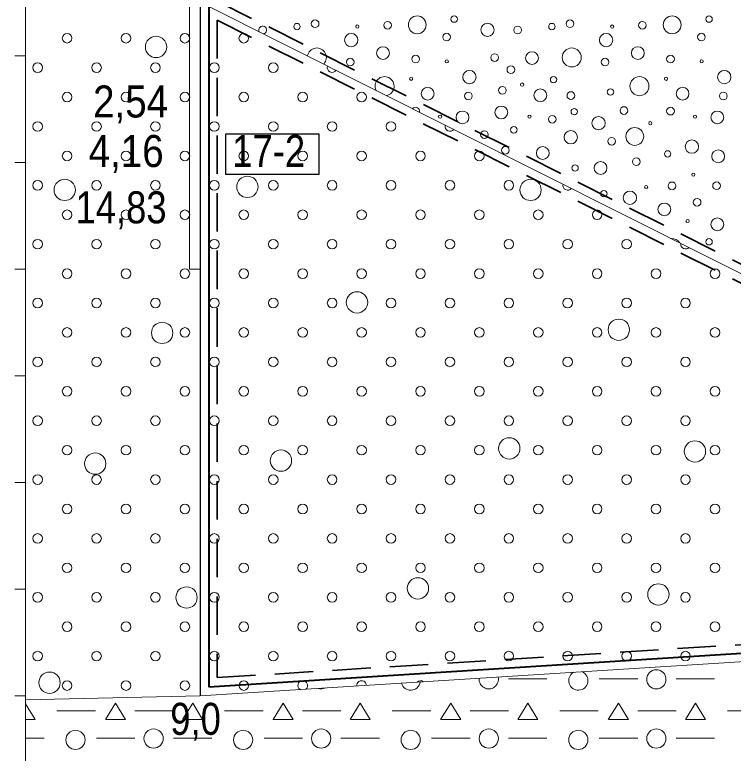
# Model space of a CAD drawing. Extents: x 640104 to 640970, y 6442278 to 6442689.
# Drawn here: x 640552.7 to 640620, y 6442553.6 to 6442622.8 of the extents above; entities that cross this region are included whole.
import ezdxf
from ezdxf.enums import TextEntityAlignment as Align

# ---------------------------------------------------------------- set-up
doc = ezdxf.new("R2010")
doc.units = 0
doc.header["$LTSCALE"] = 1.2
doc.linetypes.add('MEDIUM_DASHED', pattern=[4.5, 3, -1.5])
for name, color, linetype, lineweight in [('30', 7, 'Continuous', 13), ('31', 7, 'Continuous', 13), ('32', 7, 'Continuous', 25), ('33', 7, 'Continuous', 13), ('35', 7, 'Continuous', 35), ('41', 7, 'Continuous', 13), ('42', 7, 'Continuous', 13), ('46', 7, 'Continuous', 13), ('47', 7, 'Continuous', 13)]:
    doc.layers.add(name, color=color, linetype=linetype, lineweight=lineweight)

msp = doc.modelspace()

# ---------------------------------------------------------------- linework, layer by layer
at = {"layer": '30'}
for p, q in [((640553.71, 6442488.94), (640553.71, 6442658.94)), ((640552.71, 6442618.94), (640553.71, 6442618.94)), ((640552.71, 6442608.94), (640553.71, 6442608.94)), ((640552.71, 6442598.94), (640553.71, 6442598.94)), ((640552.71, 6442588.94), (640553.71, 6442588.94)), ((640552.71, 6442578.94), (640553.71, 6442578.94)), ((640552.71, 6442568.94), (640553.71, 6442568.94)), ((640552.71, 6442558.94), (640553.71, 6442558.94))]:
    msp.add_line(p, q, dxfattribs=at)
at = {"layer": '31'}
for points in [[(640553.71, 6442623.86), (640570.01, 6442624), (640649.72, 6442583.95), (640760.57, 6442587.97)], [(640553.71, 6442558.56), (640570.07, 6442558.94), (640649.85, 6442563.98), (640763.79, 6442536.22), (640808.67, 6442524.48), (640822.17, 6442520.94), (640837.77, 6442517.67), (640873.2, 6442509.45), (640884.27, 6442508.94), (640895.27, 6442508.94), (640947.47, 6442510.44), (640955.05, 6442510.44)]]:
    msp.add_lwpolyline(points, dxfattribs=at)
at = {"layer": '32'}
msp.add_line((640570.07, 6442648.94), (640570.07, 6442558.94), dxfattribs=at)
at = {"layer": '33'}
msp.add_lwpolyline([(640569.07, 6442623.94), (640569.07, 6442598.94), (640570.07, 6442598.94), (640570.07, 6442623.94), (640570.01, 6442623.94)], close=True, dxfattribs=at)
at = {"layer": '33', "lineweight": 25}
msp.add_lwpolyline([(640572.48, 6442611.61), (640581.19, 6442611.61), (640581.19, 6442607.81), (640572.48, 6442607.81)], close=True, dxfattribs=at)
at = {"layer": '35', "lineweight": 40}
for p, q in [((640570.87, 6442644.47), (640570.87, 6442559.79)), ((640570.87, 6442559.79), (640649.88, 6442564.78))]:
    msp.add_line(p, q, dxfattribs=at)
at = {"layer": '35', "linetype": 'MEDIUM_DASHED'}
for p, q in [((640571.67, 6442622.27), (640571.67, 6442560.65)), ((640571.67, 6442560.65), (640649.9, 6442565.58))]:
    msp.add_line(p, q, dxfattribs=at)
for points in [[(640571.67, 6442624.06), (640649.9, 6442584.76), (640753.44, 6442588.51)], [(640571.67, 6442622.27), (640649.54, 6442583.14), (640758.17, 6442587.08)]]:
    msp.add_lwpolyline(points, dxfattribs=at)
at = {"layer": '41'}
for centre, radius in [((640590.402, 6442621.833), 0.834), ((640593.86, 6442622.37), 0.3), ((640614.271, 6442621.833), 0.834), ((640617.729, 6442622.37), 0.3), ((640579.141, 6442621.671), 0.3), ((640580.839, 6442621.937), 0.36), ((640587.619, 6442621.793), 0.36), ((640596.982, 6442621.365), 0.624), ((640603.01, 6442621.671), 0.3), ((640604.708, 6442621.937), 0.36), ((640611.488, 6442621.793), 0.36), ((640584.788, 6442621.671), 0.15), ((640599.801, 6442621.35), 0.36), ((640608.657, 6442621.671), 0.15), ((640584.219, 6442620.407), 0.624), ((640593.147, 6442620.685), 0.36), ((640608.088, 6442620.407), 0.624), ((640617.016, 6442620.685), 0.36), ((640587.191, 6442619.187), 0.6), ((640601.15, 6442618.719), 0.6), ((640604.868, 6442618.775), 0.889), ((640611.06, 6442619.187), 0.6), ((640584.125, 6442618.34), 0.36), ((640590.249, 6442618.626), 0.36), ((640593.164, 6442618.41), 0.15), ((640597.648, 6442618.764), 0.36), ((640607.994, 6442618.34), 0.36), ((640614.118, 6442618.626), 0.36), ((640617.033, 6442618.41), 0.15), ((640599.167, 6442617.632), 0.36), ((640595.286, 6442616.939), 0.624), ((640619.155, 6442616.939), 0.624), ((640589.828, 6442616.778), 0.15), ((640600.22, 6442616.235), 0.15), ((640603.166, 6442616.7), 0.3), ((640611.211, 6442616.086), 0.893), ((640613.697, 6442616.778), 0.15), ((640591.379, 6442615.38), 0.6), ((640598.375, 6442615.694), 0.36), ((640601.924, 6442615.224), 0.6), ((640608.501, 6442615.536), 0.3), ((640615.248, 6442615.38), 0.6), ((640595.193, 6442615.169), 0.36), ((640604.786, 6442615.211), 0.36), ((640619.062, 6442615.169), 0.36), ((640594.637, 6442613.156), 0.6), ((640598.279, 6442613.624), 0.6), ((640605.104, 6442613.699), 0.3), ((640609.756, 6442613.804), 0.36), ((640614.118, 6442613.747), 0.36), ((640618.506, 6442613.156), 0.6), ((640592.543, 6442613.234), 0.15), ((640600.916, 6442613.234), 0.15), ((640603.045, 6442612.987), 0.36), ((640607.38, 6442612.618), 0.624), ((640616.412, 6442613.234), 0.15), ((640599.443, 6442611.992), 0.3), ((640612.224, 6442612.613), 0.15), ((640596.694, 6442611.546), 0.36), ((640604.778, 6442611.298), 0.624), ((640610.772, 6442611.376), 0.835), ((640608.604, 6442610.923), 0.36), ((640616.118, 6442610.42), 0.624), ((640598.658, 6442610.085), 0.36), ((640602.158, 6442609.817), 0.6), ((640613.853, 6442609.736), 0.3), ((640618.584, 6442609.505), 0.6), ((640607.568, 6442608.422), 0.6), ((640610.911, 6442609.009), 0.36), ((640605.182, 6442608.419), 0.3), ((640616.256, 6442607.798), 0.15), ((640611.837, 6442606.631), 0.15), ((640614.26, 6442606.742), 0.36), ((640618.427, 6442606.752), 0.36), ((640607.88, 6442606.007), 0.3), ((640610.319, 6442605.627), 0.624), ((640616.613, 6442605.21), 0.36), ((640613.544, 6442604.534), 0.6), ((640615.713, 6442603.445), 0.15), ((640618.506, 6442603.133), 0.6), ((640617.729, 6442601.501), 0.3)]:
    msp.add_circle(centre, radius, dxfattribs=at)
for centre, radius, start, end in [((640575.932, 6442621.35), 0.36, 279.37736, 207.27084), ((640580.999, 6442618.775), 0.889, 315.99627, 170.65193), ((640587.342, 6442616.086), 0.893, 280.73262, 205.91558), ((640590.249, 6442613.747), 0.36, 345.37663, 141.27157), ((640610.127, 6442603.523), 0.3, 46.35192, 80.29628), ((640614.271, 6442600.964), 0.834, 32.14579, 94.50241)]:
    msp.add_arc(centre, radius, start, end, dxfattribs=at)
at = {"layer": '42'}
for centre in [(640557.611, 6442620.579), (640563.126, 6442620.579), (640568.641, 6442620.579), (640574.157, 6442620.579), (640554.853, 6442617.821), (640560.368, 6442617.821), (640565.884, 6442617.821), (640571.399, 6442617.821), (640576.915, 6442617.821), (640557.611, 6442615.064), (640563.126, 6442615.064), (640568.641, 6442615.064), (640574.157, 6442615.064), (640579.672, 6442615.064), (640585.188, 6442615.064), (640554.853, 6442612.306), (640560.368, 6442612.306), (640565.884, 6442612.306), (640571.399, 6442612.306), (640576.915, 6442612.306), (640582.43, 6442612.306), (640587.945, 6442612.306), (640557.611, 6442609.548), (640563.126, 6442609.548), (640568.641, 6442609.548), (640574.157, 6442609.548), (640579.672, 6442609.548), (640585.188, 6442609.548), (640590.703, 6442609.548), (640596.219, 6442609.548), (640554.853, 6442606.79), (640560.368, 6442606.79), (640565.884, 6442606.79), (640571.399, 6442606.79), (640576.915, 6442606.79), (640582.43, 6442606.79), (640587.945, 6442606.79), (640593.461, 6442606.79), (640598.976, 6442606.79), (640557.611, 6442604.033), (640563.126, 6442604.033), (640568.641, 6442604.033), (640574.157, 6442604.033), (640579.672, 6442604.033), (640585.188, 6442604.033), (640590.703, 6442604.033), (640596.219, 6442604.033), (640601.734, 6442604.033), (640607.249, 6442604.033), (640554.853, 6442601.275), (640560.368, 6442601.275), (640565.884, 6442601.275), (640571.399, 6442601.275), (640576.915, 6442601.275), (640582.43, 6442601.275), (640587.945, 6442601.275), (640593.461, 6442601.275), (640598.976, 6442601.275), (640604.492, 6442601.275), (640610.007, 6442601.275), (640557.611, 6442598.517), (640563.126, 6442598.517), (640568.641, 6442598.517), (640574.157, 6442598.517), (640579.672, 6442598.517), (640585.188, 6442598.517), (640590.703, 6442598.517), (640596.219, 6442598.517), (640601.734, 6442598.517), (640607.249, 6442598.517), (640612.765, 6442598.517), (640618.28, 6442598.517), (640554.853, 6442595.76), (640560.368, 6442595.76), (640565.884, 6442595.76), (640571.399, 6442595.76), (640576.915, 6442595.76), (640582.43, 6442595.76), (640587.945, 6442595.76), (640593.461, 6442595.76), (640598.976, 6442595.76), (640604.492, 6442595.76), (640610.007, 6442595.76), (640615.523, 6442595.76), (640557.611, 6442593.002), (640563.126, 6442593.002), (640568.641, 6442593.002), (640574.157, 6442593.002), (640579.672, 6442593.002), (640585.188, 6442593.002), (640590.703, 6442593.002), (640596.219, 6442593.002), (640601.734, 6442593.002), (640607.249, 6442593.002), (640612.765, 6442593.002), (640618.28, 6442593.002), (640554.853, 6442590.244), (640560.368, 6442590.244), (640565.884, 6442590.244), (640571.399, 6442590.244), (640576.915, 6442590.244), (640582.43, 6442590.244), (640587.945, 6442590.244), (640593.461, 6442590.244), (640598.976, 6442590.244), (640604.492, 6442590.244), (640610.007, 6442590.244), (640615.523, 6442590.244), (640557.611, 6442587.486), (640563.126, 6442587.486), (640568.641, 6442587.486), (640574.157, 6442587.486), (640579.672, 6442587.486), (640585.188, 6442587.486), (640590.703, 6442587.486), (640596.219, 6442587.486), (640601.734, 6442587.486), (640607.249, 6442587.486), (640612.765, 6442587.486), (640618.28, 6442587.486), (640554.853, 6442584.729), (640560.368, 6442584.729), (640565.884, 6442584.729), (640571.399, 6442584.729), (640576.915, 6442584.729), (640582.43, 6442584.729), (640587.945, 6442584.729), (640593.461, 6442584.729), (640598.976, 6442584.729), (640604.492, 6442584.729), (640610.007, 6442584.729), (640615.523, 6442584.729), (640557.611, 6442581.971), (640563.126, 6442581.971), (640568.641, 6442581.971), (640574.157, 6442581.971), (640579.672, 6442581.971), (640585.188, 6442581.971), (640590.703, 6442581.971), (640596.219, 6442581.971), (640601.734, 6442581.971), (640607.249, 6442581.971), (640612.765, 6442581.971), (640618.28, 6442581.971), (640554.853, 6442579.213), (640560.368, 6442579.213), (640565.884, 6442579.213), (640571.399, 6442579.213), (640576.915, 6442579.213), (640582.43, 6442579.213), (640587.945, 6442579.213), (640593.461, 6442579.213), (640598.976, 6442579.213), (640604.492, 6442579.213), (640610.007, 6442579.213), (640615.523, 6442579.213), (640557.611, 6442576.456), (640563.126, 6442576.456), (640568.641, 6442576.456), (640574.157, 6442576.456), (640579.672, 6442576.456), (640585.188, 6442576.456), (640590.703, 6442576.456), (640596.219, 6442576.456), (640601.734, 6442576.456), (640607.249, 6442576.456), (640612.765, 6442576.456), (640618.28, 6442576.456), (640554.853, 6442573.698), (640560.368, 6442573.698), (640565.884, 6442573.698), (640571.399, 6442573.698), (640576.915, 6442573.698), (640582.43, 6442573.698), (640587.945, 6442573.698), (640593.461, 6442573.698), (640598.976, 6442573.698), (640604.492, 6442573.698), (640610.007, 6442573.698), (640615.523, 6442573.698), (640557.611, 6442570.94), (640563.126, 6442570.94), (640568.641, 6442570.94), (640574.157, 6442570.94), (640579.672, 6442570.94), (640585.188, 6442570.94), (640590.703, 6442570.94), (640596.219, 6442570.94), (640601.734, 6442570.94), (640607.249, 6442570.94), (640612.765, 6442570.94), (640618.28, 6442570.94), (640554.853, 6442568.182), (640560.368, 6442568.182), (640565.884, 6442568.182), (640571.399, 6442568.182), (640576.915, 6442568.182), (640582.43, 6442568.182), (640587.945, 6442568.182), (640593.461, 6442568.182), (640598.976, 6442568.182), (640604.492, 6442568.182), (640610.007, 6442568.182), (640615.523, 6442568.182), (640557.611, 6442565.425), (640563.126, 6442565.425), (640568.641, 6442565.425), (640574.157, 6442565.425), (640579.672, 6442565.425), (640585.188, 6442565.425), (640590.703, 6442565.425), (640596.219, 6442565.425), (640601.734, 6442565.425), (640607.249, 6442565.425), (640612.765, 6442565.425), (640618.28, 6442565.425), (640554.853, 6442562.667), (640560.368, 6442562.667), (640565.884, 6442562.667), (640571.399, 6442562.667), (640576.915, 6442562.667), (640582.43, 6442562.667), (640587.945, 6442562.667), (640593.461, 6442562.667), (640598.976, 6442562.667), (640604.492, 6442562.667), (640610.007, 6442562.667), (640615.523, 6442562.667), (640557.611, 6442559.909), (640563.126, 6442559.909), (640568.641, 6442559.909), (640574.157, 6442559.909)]:
    msp.add_circle(centre, 0.45, dxfattribs=at)
for centre, start, end in [((640582.43, 6442617.821), 160.35537, 326.29282), ((640593.461, 6442612.306), 163.42801, 323.22019), ((640604.492, 6442606.79), 166.53032, 320.11788), ((640615.523, 6442601.275), 169.67262, 316.97558), ((640579.672, 6442559.909), 310.24212, 236.98276), ((640585.188, 6442559.909), 1.87843, 185.34645), ((640590.703, 6442559.909), 51.51359, 135.71129)]:
    msp.add_arc(centre, 0.45, start, end, dxfattribs=at)
at = {"layer": '46'}
for p, q in [((640602.55, 6442560.54), (640598.95, 6442560.54)), ((640611.05, 6442560.54), (640607.45, 6442560.54)), ((640618.25, 6442560.54), (640614.65, 6442560.54)), ((640560.26, 6442557.55), (640556.66, 6442557.55)), ((640567.56, 6442557.54), (640563.96, 6442557.54)), ((640575.96, 6442557.55), (640572.36, 6442557.55)), ((640583.26, 6442557.54), (640579.66, 6442557.54)), ((640591.66, 6442557.55), (640588.06, 6442557.55)), ((640598.95, 6442557.54), (640595.35, 6442557.54)), ((640607.35, 6442557.55), (640603.75, 6442557.55)), ((640614.65, 6442557.54), (640611.05, 6442557.54)), ((640623.05, 6442557.55), (640619.45, 6442557.55)), ((640555.46, 6442554.98), (640553.71, 6442554.98)), ((640563.96, 6442554.99), (640560.36, 6442554.99)), ((640571.16, 6442554.98), (640567.56, 6442554.98)), ((640579.66, 6442554.99), (640576.06, 6442554.99)), ((640586.86, 6442554.98), (640583.26, 6442554.98)), ((640595.35, 6442554.99), (640591.75, 6442554.99)), ((640602.55, 6442554.98), (640598.95, 6442554.98)), ((640611.05, 6442554.99), (640607.45, 6442554.99)), ((640618.25, 6442554.98), (640614.65, 6442554.98))]:
    msp.add_line(p, q, dxfattribs=at)
for points in [[(640561.2, 6442556.72), (640561.2, 6442556.74), (640562.15, 6442558.27), (640563.08, 6442556.73), (640561.28, 6442556.74)], [(640568.42, 6442556.72), (640568.42, 6442556.74), (640569.37, 6442558.27), (640570.3, 6442556.73), (640568.5, 6442556.74)], [(640576.89, 6442556.72), (640576.9, 6442556.74), (640577.84, 6442558.27), (640578.77, 6442556.73), (640576.97, 6442556.74)], [(640584.12, 6442556.72), (640584.12, 6442556.74), (640585.07, 6442558.27), (640586, 6442556.73), (640584.2, 6442556.74)], [(640592.59, 6442556.72), (640592.59, 6442556.74), (640593.54, 6442558.27), (640594.47, 6442556.73), (640592.67, 6442556.74)], [(640599.81, 6442556.72), (640599.81, 6442556.74), (640600.76, 6442558.27), (640601.69, 6442556.73), (640599.89, 6442556.74)], [(640608.28, 6442556.72), (640608.29, 6442556.74), (640609.24, 6442558.27), (640610.17, 6442556.73), (640608.37, 6442556.74)], [(640615.51, 6442556.72), (640615.51, 6442556.74), (640616.46, 6442558.27), (640617.39, 6442556.73), (640615.59, 6442556.74)], [(640553.71, 6442558.21), (640554.61, 6442556.73), (640553.71, 6442556.73)]]:
    msp.add_lwpolyline(points, dxfattribs=at)
for centre in [(640612.794, 6442560.492), (640558.396, 6442554.815), (640565.709, 6442554.937), (640574.091, 6442554.815), (640581.404, 6442554.937), (640589.786, 6442554.815), (640597.099, 6442554.937), (640605.481, 6442554.815), (640612.794, 6442554.937)]:
    msp.add_circle(centre, 0.9, dxfattribs=at)
for centre, start, end in [((640605.481, 6442560.37), 120.0734, 67.15148), ((640597.099, 6442560.492), 173.65269, 13.57219), ((640581.404, 6442560.492), 251.4068, 295.81808), ((640589.786, 6442560.37), 195.35716, 351.86773)]:
    msp.add_arc(centre, 0.9, start, end, dxfattribs=at)
at = {"layer": '47'}
for centre in [(640565.942, 6442619.766), (640574.495, 6442606.651), (640557.388, 6442606.366), (640601.01, 6442606.366), (640584.759, 6442595.817), (640609.278, 6442593.251), (640566.512, 6442592.966), (640599.014, 6442582.132), (640616.406, 6442581.847), (640577.631, 6442580.991), (640560.239, 6442580.706), (640590.461, 6442569.017), (640612.985, 6442568.446), (640568.793, 6442568.161), (640555.963, 6442560.178)]:
    msp.add_circle(centre, 1, dxfattribs=at)

# ---------------------------------------------------------------- texts
at = {"layer": '32', "width": 0.85}
msp.add_text('9,0', height=3, dxfattribs=at).set_placement((640569.64, 6442555.29), align=Align.CENTER)
at = {"layer": '33'}
for s, width, p in [('2,54', 0.9, (640563.555, 6442613.15)), ('4,16', 0.9, (640563.14, 6442608.51)), ('17-2', 0.85, (640576.49, 6442608.52)), ('14,83', 0.85, (640562.66, 6442603.23))]:
    msp.add_text(s, height=3, dxfattribs=dict(at, width=width)).set_placement(p, align=Align.CENTER)

doc.saveas('drawing.dxf')
